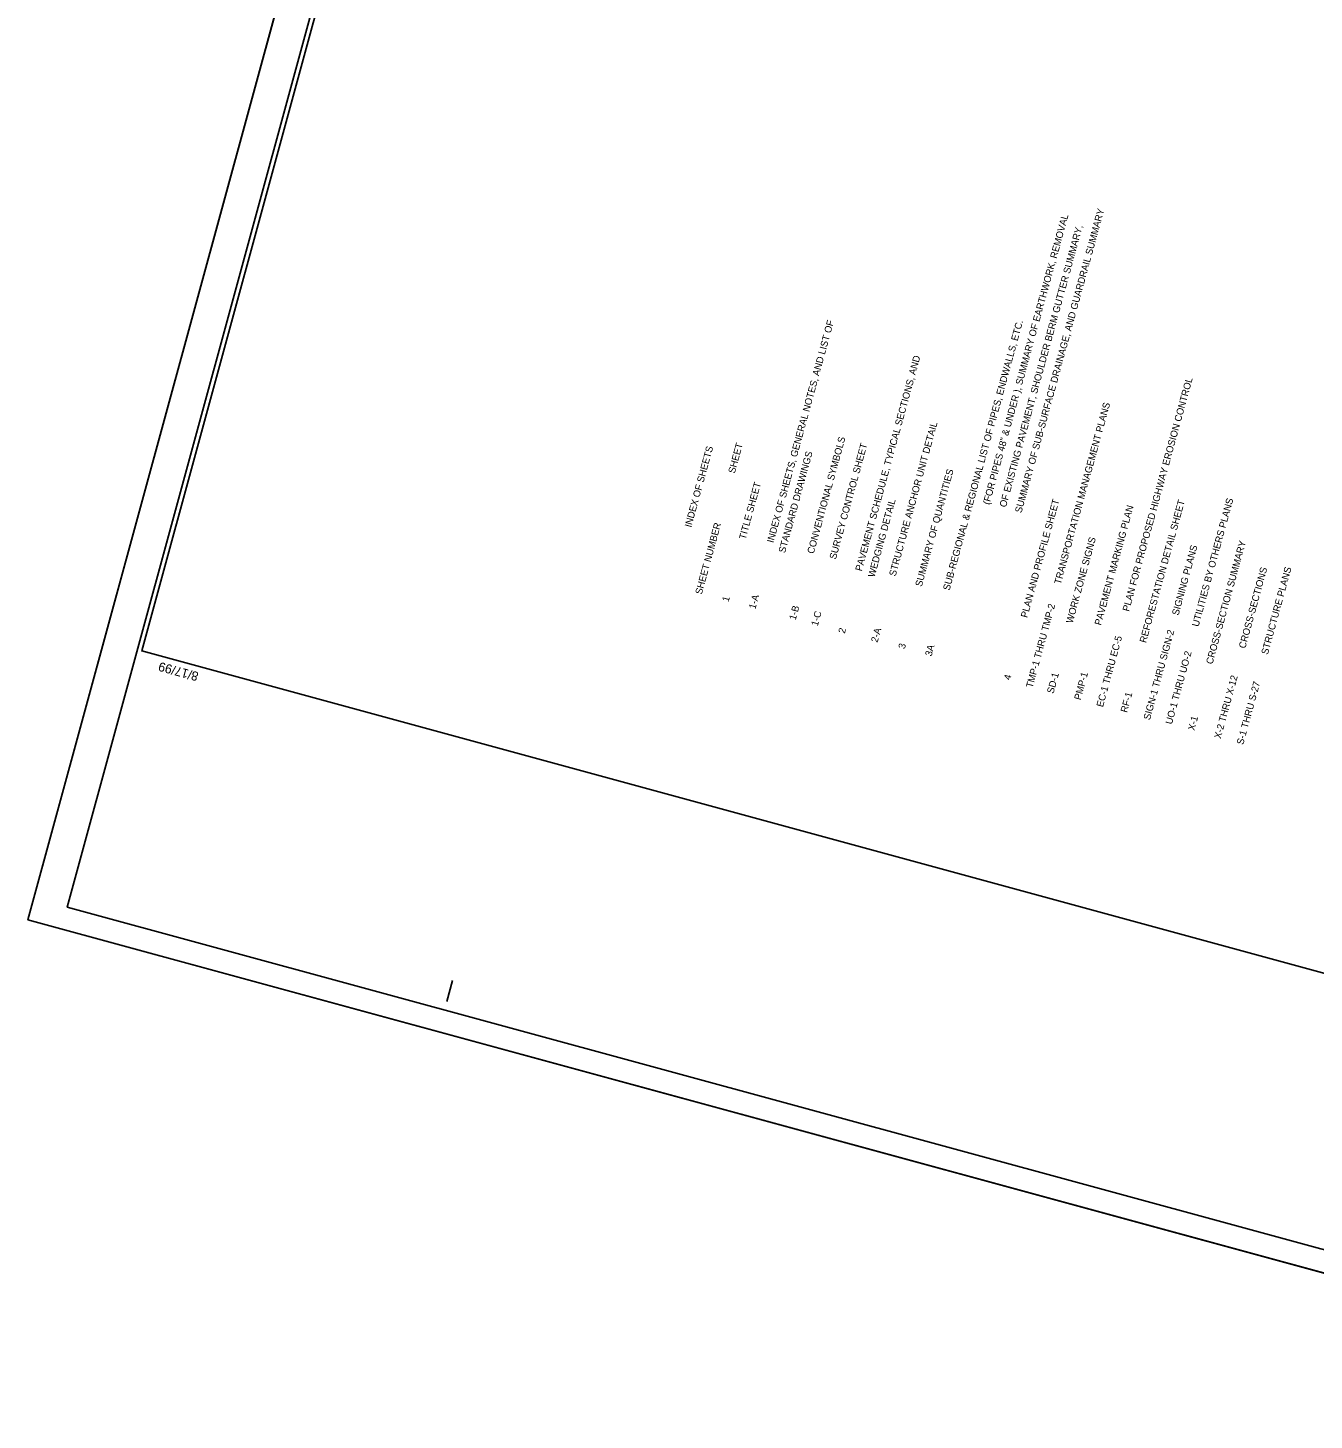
# Model space of a CAD drawing. Extents: x 2076126 to 2079903, y 925480 to 928006.
# Drawn here: x 2076126 to 2076866, y 926094 to 926895 of the extents above; entities that cross this region are included whole.
import ezdxf

# ---------------------------------------------------------------- set-up
doc = ezdxf.new("R2010")
doc.units = 0
for name, color, linetype in [('Sheet Cutting Line CELL', 7, 'Continuous'), ('Sheet Data Text CELL', 7, 'Continuous'), ('Sheet Plan CELL', 7, 'Continuous'), ('Sheet Plot Border Inside CELL', 7, 'Continuous'), ('Sheet Plot Border Outside CELL', 7, 'Continuous')]:
    doc.layers.add(name, color=color, linetype=linetype)

msp = doc.modelspace()

# ---------------------------------------------------------------- linework, layer by layer
at = {"layer": 'Sheet Cutting Line CELL'}
for p, q in [((2076568.89, 928005.87), (2076125.89, 926381.7)), ((2076125.89, 926381.7), (2077182.3, 926093.56))]:
    msp.add_line(p, q, dxfattribs=at)
at = {"layer": 'Sheet Plan CELL'}
for p, q in [((2076191.41, 926536.41), (2076191.41, 926536.41)), ((2076367, 926334.6), (2076370.29, 926346.66))]:
    msp.add_line(p, q, dxfattribs=at)
msp.add_lwpolyline([(2076586.13, 927983.55), (2076191.41, 926536.41), (2077204.41, 926260.12), (2077599.12, 927707.25)], close=True, dxfattribs=at)
at = {"layer": 'Sheet Plot Border Inside CELL'}
msp.add_lwpolyline([(2077166.43, 926111.37), (2077604.82, 927718.65), (2076587, 927996.27), (2076148.61, 926388.98)], close=True, dxfattribs=at)
at = {"layer": 'Sheet Plot Border Outside CELL'}
msp.add_lwpolyline([(2077182.3, 926093.56), (2077625.3, 927717.73), (2076568.89, 928005.87), (2076125.89, 926381.7)], close=True, dxfattribs=at)

# ---------------------------------------------------------------- texts
at = {"layer": 'Sheet Data Text CELL'}
for s, p in [('(FOR PIPES 48" & UNDER ), SUMMARY OF EARTHWORK, REMOVAL', (2076679.34, 926620.34)), ('SUMMARY OF SUB-SURFACE DRAINAGE, AND GUARDRAIL SUMMARY', (2076697.79, 926615.6)), ('OF EXISTING PAVEMENT, SHOULDER BERM GUTTER SUMMARY,', (2076688.88, 926618.87)), ('1-A                     INDEX OF SHEETS, GENERAL NOTES, AND LIST OF ', (2076544.63, 926560.26)), ('3A                      SUB-REGIONAL & REGIONAL LIST OF PIPES, ENDWALLS, ETC. ', (2076646.04, 926533.11)), ('2                       PAVEMENT SCHEDULE, TYPICAL SECTIONS, AND ', (2076596.09, 926546.23)), ('EC-1 THRU EC-5          PLAN FOR PROPOSED HIGHWAY EROSION CONTROL', (2076744.67, 926503.82)), ('TMP-1 THRU TMP-2        TRANSPORTATION MANAGEMENT PLANS', (2076704.14, 926514.87)), ('2-A                     STRUCTURE ANCHOR UNIT DETAIL ', (2076614.92, 926541.03)), ('1-B                     CONVENTIONAL SYMBOLS ', (2076567.79, 926553.95)), ('                        INDEX OF SHEETS ', (2076498.32, 926572.9)), ('SHEET NUMBER                    SHEET   ', (2076513.76, 926568.68)), ('                        STANDARD DRAWINGS', (2076552.35, 926558.16)), ('1-C                     SURVEY CONTROL SHEET', (2076580.5, 926550.48)), ('3                       SUMMARY OF QUANTITIES ', (2076630.6, 926537.32)), ('1                       TITLE SHEET', (2076529.2, 926564.47)), ('                        WEDGING DETAIL ', (2076603.81, 926544.12)), ('4                       PLAN AND PROFILE SHEET', (2076691.32, 926519.4)), ('PMP-1                   PAVEMENT MARKING PLAN', (2076731.84, 926507.89)), ('RF-1                    REFORESTATION DETAIL SHEET', (2076758.55, 926500.66)), ('UO-1 THRU UO-2          UTILITIES BY OTHERS PLANS', (2076784.36, 926493.9)), ('SD-1                    WORK ZONE SIGNS', (2076716.18, 926511.59)), ('SIGN-1 THRU SIGN-2      SIGNING PLANS', (2076771.74, 926496.43)), ('X-1                     CROSS-SECTION SUMMARY', (2076797.32, 926490.36)), ('X-2 THRU X-12           CROSS-SECTIONS', (2076812.45, 926485.67)), ('S-1 THRU S-27           STRUCTURE PLANS', (2076825.4, 926482.14))]:
    msp.add_text(s, height=4, rotation=74.7434, dxfattribs=at).set_placement(p)
at = {"layer": 'Sheet Plan CELL'}
msp.add_text('8/17/99', height=5.25, rotation=164.7434, dxfattribs=at).set_placement((2076224.52, 926524.02))

doc.saveas('drawing.dxf')
